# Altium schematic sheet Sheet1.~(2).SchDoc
size A4
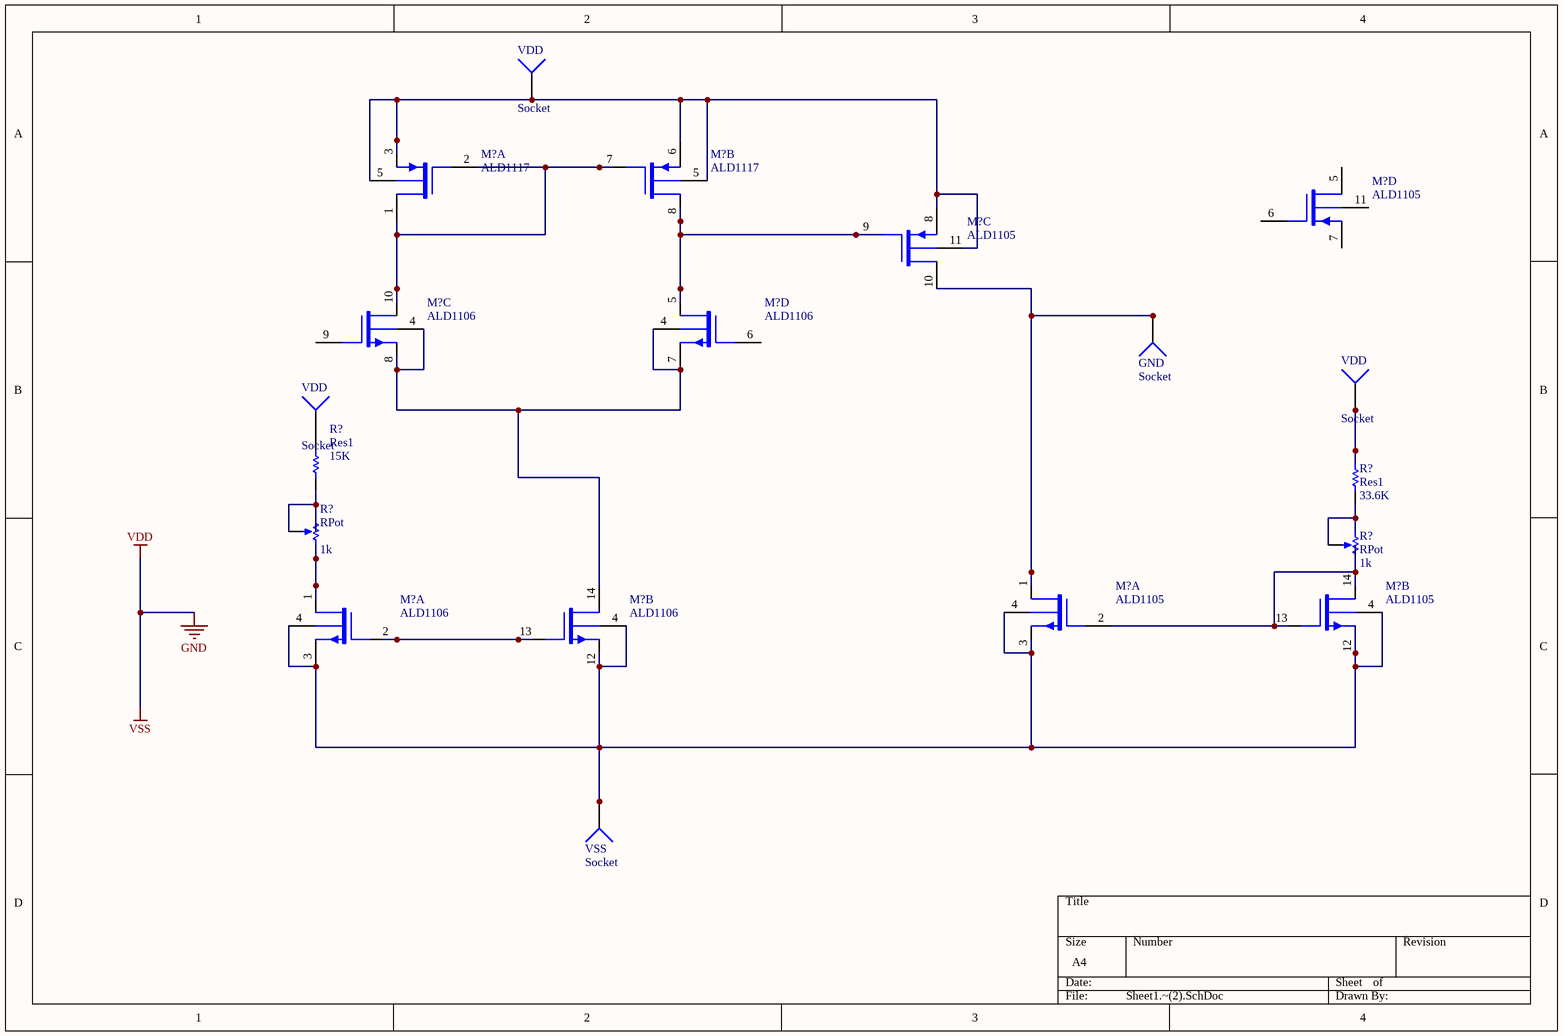
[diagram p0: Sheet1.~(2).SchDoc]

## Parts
(Parts that share a designator on the sheet are numbered #1, #2 ... from top to bottom, then left to right.)
GND  Socket  [PIN1]
M?#1  ALD1117  [DIP-8]  (part A of 2)
M?#2  ALD1117  [DIP-8]  (part B of 2)
M?#3  ALD1105  [DIP-14]  (part D of 4)
M?#4  ALD1105  [DIP-14]  (part C of 4)
M?#5  ALD1106  [DIP-14]  (part C of 4)
M?#6  ALD1106  [DIP-14]  (part D of 4)
M?#7  ALD1105  [DIP-14]  (part A of 4)
M?#8  ALD1105  [DIP-14]  (part B of 4)
M?#9  ALD1106  [DIP-14]  (part A of 4)
M?#10  ALD1106  [DIP-14]  (part B of 4)
R?#1  Res1  value 15K  [AXIAL-0.3]
R?#2  Res1  value 33.6K  [AXIAL-0.3]
R?#3  RPot  value 1k  [VR5]
R?#4  RPot  value 1k  [VR5]
VDD#1  Socket  [PIN1]
VDD#2  Socket  [PIN1]
VDD#3  Socket  [PIN1]
VSS  Socket  [PIN1]

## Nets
NetGND_1: GND.1 M?#4.10(DP2) M?#7.1(DN1)
NetM?#1_1: M?#1.1(DP1) M?#1.2(GP1) M?#2.7(GP2) M?#5.10(DN3)
NetM?#1_3: M?#1.3(SP1) M?#1.5(V+) M?#2.5(V+) M?#2.6(SP2) M?#4.8(SP2) M?#4.11(V+) VDD#1.1
NetM?#2_8: M?#2.8(DP2) M?#4.9(GP2) M?#6.5(DN4)
NetM?#5_4: M?#5.4(V-) M?#5.8(SN3) M?#6.4(V-) M?#6.7(SN4) M?#10.14(DN2)
NetM?#7_2: M?#7.2(GN1) M?#8.13(GN2) M?#8.14(DN2) R?#4.3(BOT)
NetM?#7_3: M?#7.3(SN1) M?#7.4(V-) M?#8.4(V-) M?#8.12(SN2) M?#9.3(SN1) M?#9.4(V-) M?#10.4(V-) M?#10.12(SN2) VSS.1
NetM?#9_1: M?#9.1(DN1) R?#3.3(BOT)
NetM?#9_2: M?#9.2(GN1) M?#10.13(GN2)
NetR?#1_1: R?#1.1 R?#3.1(TOP) R?#3.2(TAP)
NetR?#1_2: R?#1.2 VDD#3.1
NetR?#2_1: R?#2.1 R?#4.1(TOP) R?#4.2(TAP)
NetR?#2_2: R?#2.2 VDD#2.1

Not connected (* = marked no-connect by the designer): M?#3 5(DP1) 6(GP1) 7(SP1) 11(V+); M?#5 9(GN3); M?#6 6(GN4)

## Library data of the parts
M?#1 M?#2 = ALD1117: Dual P-channel matched MOSFET array
M?#3 M?#4 M?#7 M?#8 = ALD1105: Dual P-channel and dual N-channel matched MOSFET array
M?#5 M?#6 M?#9 M?#10 = ALD1106: Quad N-channel matched MOSFET array
R?#1 R?#2 = Res1: Resistor
R?#3 R?#4 = RPot: Potentiometer; Sim Note: Enter the Resistance value and the set point into parameter fields.; Set Position: 0.5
